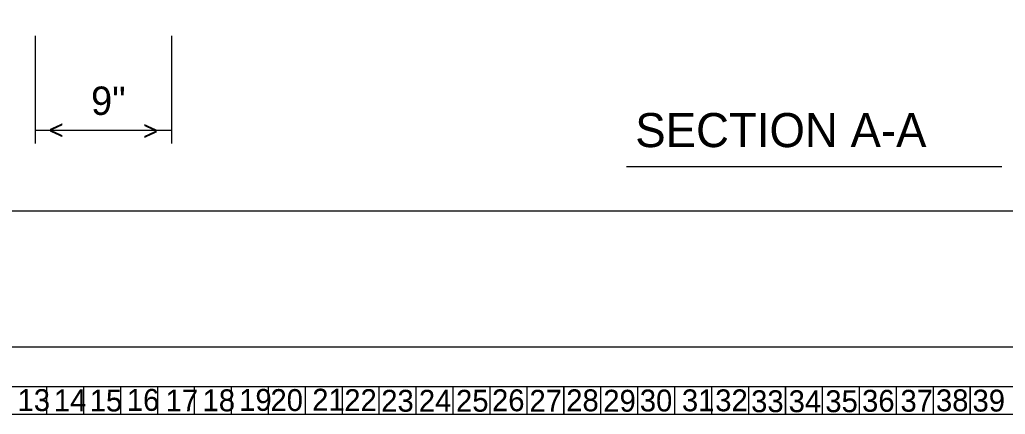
# Model space of a CAD drawing. Extents: x 0 to 3.31, y -0.03 to 1.83.
# Drawn here: x 0.3128 to 0.7646, y -0.0308 to 0.1501 of the extents above; entities that cross this region are included whole.
import ezdxf

# ---------------------------------------------------------------- set-up
doc = ezdxf.new("R2010")
doc.units = 0
for name, color, linetype in [('13', 7, 'Continuous'), ('14', 7, 'Continuous'), ('15', 7, 'Continuous'), ('16', 7, 'Continuous'), ('17', 7, 'Continuous'), ('18', 7, 'Continuous'), ('19', 7, 'Continuous'), ('20', 7, 'Continuous'), ('21', 7, 'Continuous'), ('22', 7, 'Continuous'), ('23', 7, 'Continuous'), ('24', 7, 'Continuous'), ('25', 7, 'Continuous'), ('26', 7, 'Continuous'), ('27', 7, 'Continuous'), ('28', 7, 'Continuous'), ('29', 7, 'Continuous'), ('30', 7, 'Continuous'), ('31', 7, 'Continuous'), ('32', 7, 'Continuous'), ('33', 7, 'Continuous'), ('34', 7, 'Continuous'), ('35', 7, 'Continuous'), ('36', 7, 'Continuous'), ('37', 7, 'Continuous'), ('38', 7, 'Continuous'), ('39', 7, 'Continuous'), ('55', 7, 'Continuous'), ('57', 7, 'Continuous'), ('62', 7, 'Continuous'), ('63', 7, 'Continuous')]:
    doc.layers.add(name, color=color, linetype=linetype)

msp = doc.modelspace()

# ---------------------------------------------------------------- linework, layer by layer
at = {"layer": '55'}
for p, q in [((0.31991, 0.14266), (0.31991, 0.0934)), ((0.3824, 0.14266), (0.3824, 0.0934)), ((0.3824, 0.09923), (0.31991, 0.09923))]:
    msp.add_line(p, q, dxfattribs=at)
at = {"layer": '57'}
msp.add_line((0.59088, 0.08275), (0.76294, 0.08275), dxfattribs=at)
at = {"layer": '62'}
for p, q in [((0.10494, -0.01804), (1.17174, -0.01804)), ((0.32508, -0.01804), (0.32508, -0.03074)), ((0.34201, -0.01804), (0.34201, -0.03074)), ((0.35894, -0.01804), (0.35894, -0.03074)), ((0.37588, -0.01804), (0.37588, -0.03074)), ((0.39281, -0.01804), (0.39281, -0.03074)), ((0.40974, -0.01804), (0.40974, -0.03074)), ((0.42668, -0.01804), (0.42668, -0.03074)), ((0.44361, -0.01804), (0.44361, -0.03074)), ((0.46054, -0.01804), (0.46054, -0.03074)), ((0.47748, -0.01804), (0.47748, -0.03074)), ((0.49441, -0.01804), (0.49441, -0.03074)), ((0.51134, -0.01804), (0.51134, -0.03074)), ((0.52828, -0.01804), (0.52828, -0.03074)), ((0.54521, -0.01804), (0.54521, -0.03074)), ((0.56214, -0.01804), (0.56214, -0.03074)), ((0.57908, -0.01804), (0.57908, -0.03074)), ((0.59601, -0.01804), (0.59601, -0.03074)), ((0.61294, -0.01804), (0.61294, -0.03074)), ((0.62988, -0.01804), (0.62988, -0.03074)), ((0.64681, -0.01804), (0.64681, -0.03074)), ((0.66374, -0.01804), (0.66374, -0.03074)), ((0.68068, -0.01804), (0.68068, -0.03074)), ((0.69761, -0.01804), (0.69761, -0.03074)), ((0.71454, -0.01804), (0.71454, -0.03074)), ((0.73148, -0.01804), (0.73148, -0.03074)), ((0.74841, -0.01804), (0.74841, -0.03074)), ((0.10496, -0.0181), (1.17175, -0.0181)), ((0.32509, -0.0181), (0.32509, -0.0308)), ((0.34202, -0.0181), (0.34202, -0.0308)), ((0.35896, -0.0181), (0.35896, -0.0308)), ((0.37589, -0.0181), (0.37589, -0.0308)), ((0.39282, -0.0181), (0.39282, -0.0308)), ((0.40976, -0.0181), (0.40976, -0.0308)), ((0.42669, -0.0181), (0.42669, -0.0308)), ((0.44362, -0.0181), (0.44362, -0.0308)), ((0.46056, -0.0181), (0.46056, -0.0308)), ((0.47749, -0.0181), (0.47749, -0.0308)), ((0.49442, -0.0181), (0.49442, -0.0308)), ((0.51136, -0.0181), (0.51136, -0.0308)), ((0.52829, -0.0181), (0.52829, -0.0308)), ((0.54522, -0.0181), (0.54522, -0.0308)), ((0.56216, -0.0181), (0.56216, -0.0308)), ((0.57909, -0.0181), (0.57909, -0.0308)), ((0.59602, -0.0181), (0.59602, -0.0308)), ((0.61296, -0.0181), (0.61296, -0.0308)), ((0.62989, -0.0181), (0.62989, -0.0308)), ((0.64682, -0.0181), (0.64682, -0.0308)), ((0.66376, -0.0181), (0.66376, -0.0308)), ((0.68069, -0.0181), (0.68069, -0.0308)), ((0.69762, -0.0181), (0.69762, -0.0308)), ((0.71456, -0.0181), (0.71456, -0.0308)), ((0.73149, -0.0181), (0.73149, -0.0308)), ((0.74842, -0.0181), (0.74842, -0.0308)), ((0.10494, -0.03074), (1.17174, -0.03074)), ((0.10496, -0.0308), (1.17175, -0.0308))]:
    msp.add_line(p, q, dxfattribs=at)
msp.add_lwpolyline([(2.72918, 1.77077), (0.10418, 1.77077), (0.10418, 0.06244), (2.72918, 0.06244)], close=True, dxfattribs=at)
at = {"layer": '63'}
msp.add_line((2.83333, 0), (0, 0), dxfattribs=at)
msp.add_line((2.83333, 0), (0, 0), dxfattribs=at)
msp.add_line((2.83333, 0), (0, 0), dxfattribs=at)
msp.add_lwpolyline([(2.72918, 1.77077), (0.10418, 1.77077), (0.10418, 0.06244), (2.72918, 0.06244)], close=True, dxfattribs=at)

# ---------------------------------------------------------------- texts
at = {"layer": '13'}
for p in [(0.31181, -0.02928), (0.31182, -0.02933)]:
    msp.add_text('13', height=0.01, dxfattribs=at).set_placement(p)
at = {"layer": '14'}
for p in [(0.32844, -0.02939), (0.32846, -0.02944)]:
    msp.add_text('14', height=0.01, dxfattribs=at).set_placement(p)
at = {"layer": '15'}
for p in [(0.34488, -0.02946), (0.34489, -0.02951)]:
    msp.add_text('15', height=0.01, dxfattribs=at).set_placement(p)
at = {"layer": '16'}
for p in [(0.3619, -0.02918), (0.36191, -0.02923)]:
    msp.add_text('16', height=0.01, dxfattribs=at).set_placement(p)
at = {"layer": '17'}
for p in [(0.3797, -0.02946), (0.37971, -0.02951)]:
    msp.add_text('17', height=0.01, dxfattribs=at).set_placement(p)
at = {"layer": '18'}
for p in [(0.39663, -0.02938), (0.39664, -0.02943)]:
    msp.add_text('18', height=0.01, dxfattribs=at).set_placement(p)
at = {"layer": '19'}
for p in [(0.4134, -0.02918), (0.41342, -0.02923)]:
    msp.add_text('19', height=0.01, dxfattribs=at).set_placement(p)
at = {"layer": '20'}
for p in [(0.42774, -0.02926), (0.42776, -0.02931)]:
    msp.add_text('20', height=0.01, dxfattribs=at).set_placement(p)
at = {"layer": '21'}
for p in [(0.44688, -0.02909), (0.44689, -0.02914)]:
    msp.add_text('21', height=0.01, dxfattribs=at).set_placement(p)
at = {"layer": '22'}
for p in [(0.46158, -0.02929), (0.46159, -0.02934)]:
    msp.add_text('22', height=0.01, dxfattribs=at).set_placement(p)
at = {"layer": '23'}
for p in [(0.47852, -0.02958), (0.47853, -0.02963)]:
    msp.add_text('23', height=0.01, dxfattribs=at).set_placement(p)
at = {"layer": '24'}
for p in [(0.49576, -0.02958), (0.49577, -0.02963)]:
    msp.add_text('24', height=0.01, dxfattribs=at).set_placement(p)
at = {"layer": '25'}
for p in [(0.51281, -0.02958), (0.51282, -0.02963)]:
    msp.add_text('25', height=0.01, dxfattribs=at).set_placement(p)
at = {"layer": '26'}
for p in [(0.52931, -0.02936), (0.52932, -0.02941)]:
    msp.add_text('26', height=0.01, dxfattribs=at).set_placement(p)
at = {"layer": '27'}
for p in [(0.54648, -0.02958), (0.54649, -0.02963)]:
    msp.add_text('27', height=0.01, dxfattribs=at).set_placement(p)
at = {"layer": '28'}
for p in [(0.56333, -0.02938), (0.56334, -0.02943)]:
    msp.add_text('28', height=0.01, dxfattribs=at).set_placement(p)
at = {"layer": '29'}
for p in [(0.58033, -0.02956), (0.58034, -0.02961)]:
    msp.add_text('29', height=0.01, dxfattribs=at).set_placement(p)
at = {"layer": '30'}
for p in [(0.59706, -0.02946), (0.59707, -0.02951)]:
    msp.add_text('30', height=0.01, dxfattribs=at).set_placement(p)
at = {"layer": '31'}
for p in [(0.61636, -0.02938), (0.61637, -0.02943)]:
    msp.add_text('31', height=0.01, dxfattribs=at).set_placement(p)
at = {"layer": '32'}
for p in [(0.63163, -0.02938), (0.63165, -0.02943)]:
    msp.add_text('32', height=0.01, dxfattribs=at).set_placement(p)
at = {"layer": '33'}
for p in [(0.64808, -0.02978), (0.64809, -0.02983)]:
    msp.add_text('33', height=0.01, dxfattribs=at).set_placement(p)
at = {"layer": '34'}
for p in [(0.66527, -0.02978), (0.66528, -0.02984)]:
    msp.add_text('34', height=0.01, dxfattribs=at).set_placement(p)
at = {"layer": '35'}
for p in [(0.68209, -0.02978), (0.68211, -0.02984)]:
    msp.add_text('35', height=0.01, dxfattribs=at).set_placement(p)
at = {"layer": '36'}
for p in [(0.69895, -0.02958), (0.69896, -0.02964)]:
    msp.add_text('36', height=0.01, dxfattribs=at).set_placement(p)
at = {"layer": '37'}
for p in [(0.71654, -0.02958), (0.71655, -0.02964)]:
    msp.add_text('37', height=0.01, dxfattribs=at).set_placement(p)
at = {"layer": '38'}
for p in [(0.73281, -0.02938), (0.73282, -0.02943)]:
    msp.add_text('38', height=0.01, dxfattribs=at).set_placement(p)
at = {"layer": '39'}
for p in [(0.74958, -0.0295), (0.74959, -0.02955)]:
    msp.add_text('39', height=0.01, dxfattribs=at).set_placement(p)
at = {"layer": '55'}
msp.add_text('>', height=0.00868, rotation=180, dxfattribs=at).set_placement((0.33293, 0.10356))
msp.add_text('>', height=0.00868, rotation=180, dxfattribs=at).set_placement((0.33293, 0.10356))
msp.add_text('>', height=0.00868, dxfattribs=at).set_placement((0.36939, 0.09489))
msp.add_text('>', height=0.00868, dxfattribs=at).set_placement((0.36939, 0.09489))
at = {"layer": '57'}
for s, height, p in [('9"', 0.013017, (0.3455, 0.10642)), ('SECTION A-A', 0.015625, (0.59496, 0.09166))]:
    msp.add_text(s, height=height, dxfattribs=at).set_placement(p)

doc.saveas('drawing.dxf')
